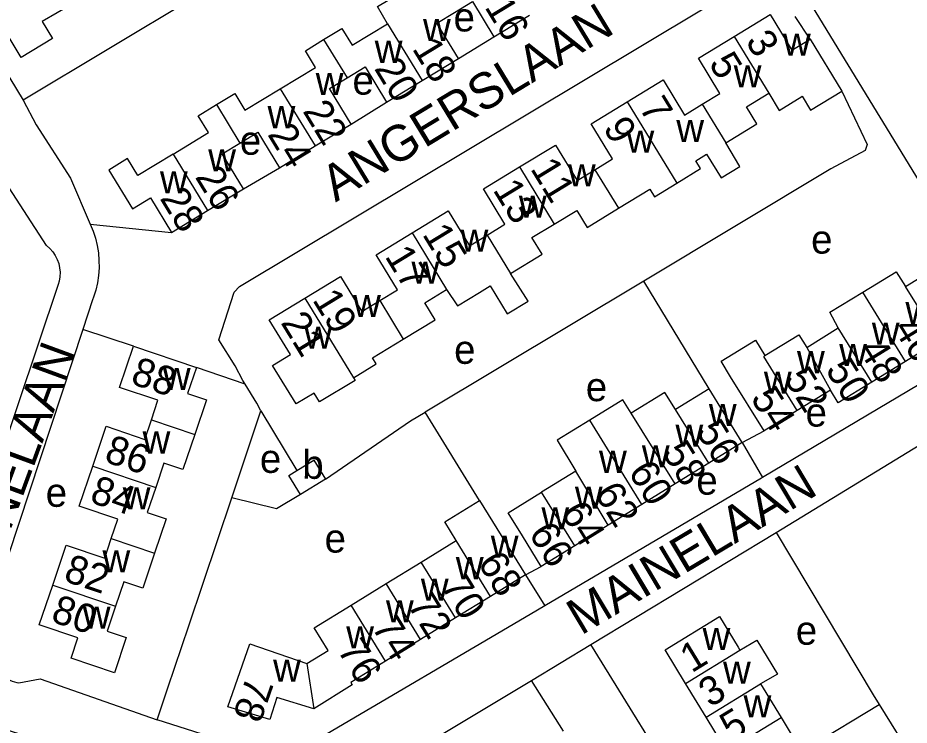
# Model space of a CAD drawing. Extents: x 157768 to 159790, y 387230 to 389604.
# Drawn here: x 158224.1 to 158348.2, y 388360.7 to 388459.2 of the extents above; entities that cross this region are included whole.
import ezdxf

# ---------------------------------------------------------------- set-up
doc = ezdxf.new("R2010")
doc.units = 0
for name, color, linetype in [('BLT_Basislijn', 7, 'Continuous'), ('BLT_Bebouwing', 7, 'Continuous'), ('BLT_Centroide', 7, 'Continuous'), ('BLT_Huisnummer', 7, 'Continuous'), ('BLT_Huisnummer_ tussenligend', 7, 'Continuous'), ('BLT_Onderverdeling_panden', 7, 'Continuous'), ('BLT_Straatnaam', 7, 'Continuous')]:
    doc.layers.add(name, color=color, linetype=linetype)

msp = doc.modelspace()

# ---------------------------------------------------------------- linework, layer by layer
at = {"layer": 'BLT_Basislijn'}
for p, q in [((158304.74, 388495.73), (158224.85, 388447.7)), ((158212.8, 388467.55), (158224.85, 388447.7)), ((158228.09, 388427.45), (158207.21, 388459.77)), ((158334.4, 388456.22), (158332.34, 388459.35)), ((158285.45, 388453.52), (158290.4, 388456.54)), ((158270.51, 388444.39), (158275.46, 388447.45)), ((158255.51, 388435.36), (158260.52, 388438.31)), ((158234.19, 388430.43), (158245.51, 388429.28)), ((158311.26, 388422.52), (158280.82, 388404.27)), ((158320.33, 388407.51), (158311.26, 388422.52)), ((158229.72, 388422.06), (158213.16, 388372.67)), ((158234.53, 388419.89), (158233.16, 388415.76)), ((158233.16, 388415.76), (158219.39, 388374.05)), ((158240.2, 388413.45), (158233.16, 388415.76)), ((158362.4, 388415.74), (158327.79, 388395.17)), ((158255.76, 388408.14), (158248.97, 388410.49)), ((158253.89, 388392.34), (158257.96, 388404.43)), ((158288.4, 388391.97), (158280.82, 388404.27)), ((158324.95, 388400.02), (158327.99, 388401.64)), ((158324.95, 388400.02), (158327.79, 388395.17)), ((158303.89, 388371.88), (158329.67, 388387.52)), ((158294.79, 388381.61), (158296.97, 388382.76)), ((158294.79, 388381.61), (158297.47, 388377.27)), ((158295.63, 388366.87), (158303.89, 388371.88)), ((158300.07, 388359.82), (158295.63, 388366.87)), ((158333.21, 388357.04), (158344.03, 388363.53))]:
    msp.add_line(p, q, dxfattribs=at)
for points in [[(158255.76, 388408.14), (158255.42, 388408.68), (158254.36, 388410.69), (158252.11, 388414.33), (158254.23, 388420.97), (158254.99, 388421.77), (158327.25, 388465.12), (158328.19, 388465.65), (158328.83, 388464.68)], [(158360.28, 388419.09), (158358.56, 388421.8), (158334.74, 388460.77)], [(158338.81, 388448.98), (158342.33, 388441.54), (158342.05, 388440.69), (158337.29, 388438.17), (158311.26, 388422.52)], [(158224.85, 388447.7), (158226.67, 388444.26), (158231.45, 388436.84), (158234.19, 388430.43)], [(158234.19, 388430.43), (158234.59, 388429.47), (158234.91, 388428.48), (158235.16, 388427.47), (158235.33, 388426.44), (158235.41, 388425.4), (158235.42, 388424.35), (158235.35, 388423.31), (158235.2, 388422.28), (158234.97, 388421.27), (158234.66, 388420.27), (158234.53, 388419.89)], [(158228.09, 388427.45), (158228.56, 388427.05), (158228.97, 388426.59), (158229.32, 388426.08), (158229.6, 388425.54), (158229.81, 388424.96), (158229.94, 388424.35), (158229.99, 388423.74), (158229.96, 388423.12), (158229.86, 388422.51), (158229.72, 388422.06)], [(158257.96, 388404.43), (158257.41, 388405.53), (158255.76, 388408.14)], [(158257.96, 388404.43), (158262.94, 388396.12)], [(158266.94, 388394.92), (158278.76, 388403.04), (158280.82, 388404.27)], [(158329.67, 388387.52), (158351.49, 388400.82), (158354.62, 388401.86), (158356.15, 388401.86), (158358.13, 388401.3), (158360.43, 388398.73), (158376, 388372.54), (158376.85, 388371.15)], [(158327.79, 388395.17), (158327.62, 388395.07), (158297.47, 388377.27)], [(158263.46, 388392.8), (158260.12, 388390.79), (158253.89, 388392.34)], [(158243.5, 388361.42), (158244.99, 388365.88), (158247.93, 388374.52), (158253.89, 388392.34)], [(158329.67, 388387.52), (158343.18, 388364.91), (158344.03, 388363.53)], [(158297.47, 388377.27), (158295.43, 388376.07), (158265.59, 388358.55), (158261.05, 388357.55), (158254.9, 388357.79), (158243.5, 388361.42)], [(158219.39, 388374.05), (158219.25, 388373.36), (158219.2, 388372.67), (158219.23, 388371.97), (158219.33, 388371.28), (158219.52, 388370.61), (158219.78, 388369.97), (158220.11, 388369.35), (158220.51, 388368.78), (158220.98, 388368.26), (158221.5, 388367.8), (158222.07, 388367.4), (158222.68, 388367.07), (158223.32, 388366.8), (158223.99, 388366.62), (158224.27, 388366.57)], [(158318.74, 388347.85), (158317.77, 388349.42), (158303.89, 388371.88)], [(158216.32, 388362.01), (158245.98, 388352.56), (158258.32, 388349.1), (158262.21, 388348.81), (158266.48, 388349.4), (158295.63, 388366.87)], [(158224.27, 388366.57), (158227.24, 388367.13), (158243.5, 388361.42)], [(158344.03, 388363.53), (158348.79, 388355.84), (158349.73, 388354.3)]]:
    msp.add_lwpolyline(points, dxfattribs=at)
at = {"layer": 'BLT_Bebouwing'}
for p, q in [((158290.4, 388456.54), (158295.36, 388459.56)), ((158334.4, 388456.22), (158338.81, 388448.98)), ((158280.4, 388450.46), (158285.45, 388453.52)), ((158260.52, 388438.31), (158265.49, 388441.34)), ((158250.53, 388432.33), (158255.51, 388435.36)), ((158245.51, 388429.28), (158250.53, 388432.33)), ((158333.93, 388413.28), (158338.33, 388415.99)), ((158352.35, 388414.2), (158347.67, 388411.31)), ((158240.2, 388413.45), (158248.97, 388410.49)), ((158347.67, 388411.31), (158342.99, 388408.43)), ((158320.33, 388407.51), (158315.67, 388404.63)), ((158337.22, 388407.33), (158332.6, 388404.48)), ((158332.6, 388404.48), (158327.99, 388401.64)), ((158324.95, 388400.02), (158320.29, 388397.14)), ((158320.29, 388397.14), (158315.63, 388394.27)), ((158301.77, 388396.06), (158297.02, 388393.13)), ((158266.94, 388394.92), (158263.46, 388392.8)), ((158315.63, 388394.27), (158310.96, 388391.39)), ((158288.4, 388391.97), (158294.79, 388381.61)), ((158310.96, 388391.39), (158306.3, 388388.51)), ((158306.3, 388388.51), (158301.64, 388385.64)), ((158280.25, 388383.39), (158285.12, 388386.39)), ((158301.64, 388385.64), (158296.97, 388382.76)), ((158275.39, 388380.39), (158280.25, 388383.39)), ((158294.79, 388381.61), (158289.92, 388378.61)), ((158270.52, 388377.39), (158275.39, 388380.39)), ((158289.92, 388378.61), (158285.06, 388375.61)), ((158285.06, 388375.61), (158280.19, 388372.6)), ((158280.19, 388372.6), (158275.32, 388369.6)), ((158319.93, 388361.8), (158317.07, 388366.49)), ((158327.5, 388366.41), (158330.36, 388361.72)), ((158322.79, 388357.11), (158319.93, 388361.8)), ((158330.36, 388361.72), (158333.21, 388357.04))]:
    msp.add_line(p, q, dxfattribs=at)
for points in [[(158231.67, 388461.1), (158227.5, 388458.67), (158228.95, 388456.3), (158224.6, 388453.65), (158221.07, 388459.45), (158224.94, 388461.8), (158220.75, 388468.67), (158225.35, 388471.47)], [(158275.59, 388458.36), (158274.18, 388460.75), (158279.08, 388463.73), (158281.64, 388465.29)], [(158284.9, 388459.93), (158287.41, 388461.45), (158290.4, 388456.54)], [(158285.45, 388453.52), (158282.46, 388458.44), (158284.9, 388459.93)], [(158323.84, 388456.59), (158328.83, 388459.64), (158331.86, 388454.67), (158334.4, 388456.22)], [(158266.69, 388456.15), (158269.24, 388457.71), (158270.67, 388455.36), (158275.59, 388458.36)], [(158260.64, 388449.3), (158265.55, 388452.28), (158264.14, 388454.6), (158266.69, 388456.15)], [(158319.39, 388447.14), (158321.84, 388448.64), (158318.85, 388453.55), (158323.84, 388456.59)], [(158269.94, 388450.81), (158272.47, 388452.35), (158275.46, 388447.45)], [(158270.51, 388444.39), (158267.51, 388449.33), (158269.94, 388450.81)], [(158275.46, 388447.45), (158280.4, 388450.46)], [(158308.93, 388447.49), (158313.94, 388450.54), (158316.93, 388445.64), (158319.39, 388447.14)], [(158251.77, 388447.09), (158254.32, 388448.65), (158255.74, 388446.32), (158260.64, 388449.3)], [(158322.65, 388441.79), (158326.98, 388444.43), (158325.55, 388446.77), (158328.67, 388448.67)], [(158328.67, 388448.67), (158330.09, 388446.29), (158333.24, 388448.21), (158333.31, 388448.25), (158334.48, 388446.34), (158338.81, 388448.98)], [(158304.43, 388438.03), (158306.91, 388439.53), (158303.92, 388444.43), (158308.93, 388447.49)], [(158245.74, 388440.21), (158250.64, 388443.2), (158249.21, 388445.54), (158251.77, 388447.09)], [(158265.49, 388441.34), (158270.51, 388444.39)], [(158255.03, 388441.73), (158257.51, 388443.24), (158260.52, 388438.31)], [(158255.51, 388435.36), (158252.55, 388440.22), (158255.03, 388441.73)], [(158293.93, 388438.41), (158298.94, 388441.46), (158301.96, 388436.52), (158304.43, 388438.03)], [(158318.51, 388439.27), (158320, 388440.17), (158322.01, 388436.88), (158324.62, 388438.48), (158322.65, 388441.79)], [(158245.74, 388440.21), (158240.83, 388437.23), (158239.4, 388439.58), (158236.77, 388437.98), (158240.06, 388432.58), (158242.57, 388434.11), (158245.51, 388429.28)], [(158315.83, 388436.16), (158319.16, 388438.19), (158318.51, 388439.27)], [(158289.46, 388428.93), (158291.93, 388430.43), (158288.92, 388435.35), (158293.93, 388438.41)], [(158307.71, 388432.65), (158312.1, 388435.32), (158312.74, 388434.27), (158315.83, 388436.16)], [(158279.02, 388429.24), (158284.03, 388432.29), (158287, 388427.42), (158289.46, 388428.93)], [(158298.78, 388430.45), (158301.92, 388432.36), (158303.37, 388430), (158307.71, 388432.65)], [(158292.72, 388423.58), (158297.1, 388426.25), (158295.69, 388428.57), (158298.78, 388430.45)], [(158274.49, 388419.8), (158276.97, 388421.31), (158274, 388426.18), (158279.02, 388429.24)], [(158283.81, 388421.36), (158285.33, 388419.07), (158288.37, 388420.92), (158289.87, 388421.84), (158292.24, 388417.96), (158295.15, 388419.73), (158292.72, 388423.58)], [(158341.76, 388420.99), (158346.38, 388423.81), (158347.68, 388421.76)], [(158347.68, 388421.76), (158352.35, 388424.64), (158357.02, 388417.08)], [(158264.08, 388420.15), (158269.04, 388423.17), (158272.02, 388418.3), (158274.49, 388419.8)], [(158277.77, 388414.44), (158282.2, 388417.14), (158280.76, 388419.5), (158283.81, 388421.36)], [(158270.85, 388409.05), (158271.07, 388408.69), (158266.12, 388405.68), (158265.36, 388406.92), (158262.85, 388405.4), (158259.58, 388410.75), (158262.07, 388412.27), (158259.11, 388417.12), (158264.08, 388420.15)], [(158338.33, 388415.99), (158337.16, 388418.18), (158341.76, 388420.99)], [(158328.12, 388412.13), (158332.84, 388415.04), (158333.93, 388413.28)], [(158270.85, 388409.05), (158274, 388410.97), (158273.48, 388411.83), (158277.77, 388414.44)], [(158327.99, 388401.64), (158323.34, 388409.18), (158322, 388411.34), (158326.8, 388414.3), (158328.12, 388412.13)], [(158242.71, 388403.19), (158243.62, 388405.91), (158238.26, 388407.71), (158240.2, 388413.45)], [(158248.97, 388410.49), (158247.74, 388406.86), (158250.37, 388405.97), (158248.75, 388401.15)], [(158324.95, 388400.02), (158322.33, 388404.27), (158320.33, 388407.51)], [(158342.99, 388408.43), (158338.32, 388405.55), (158337.22, 388407.33)], [(158315.67, 388404.63), (158314.2, 388407.01), (158309.5, 388404.1)], [(158309.5, 388404.1), (158308.34, 388405.99), (158303.75, 388403.16)], [(158234.54, 388396.74), (158236.41, 388402.29), (158241.79, 388400.47), (158242.71, 388403.19)], [(158303.75, 388403.16), (158299.18, 388400.34), (158301.77, 388396.06)], [(158248.75, 388401.15), (158247.1, 388396.27), (158244.45, 388397.16), (158243.31, 388393.78)], [(158262.94, 388396.12), (158265.32, 388397.57), (158266.94, 388394.92)], [(158237.13, 388386.65), (158238.05, 388389.37), (158232.67, 388391.19), (158234.54, 388396.74)], [(158263.46, 388392.8), (158261.84, 388395.45), (158262.94, 388396.12)], [(158243.31, 388393.78), (158242.14, 388390.3), (158244.76, 388389.41), (158243.14, 388384.62)], [(158296.97, 388382.76), (158294.35, 388387.02), (158292.35, 388390.25), (158297.02, 388393.13)], [(158285.12, 388386.39), (158283.58, 388389), (158288.4, 388391.97)], [(158228.97, 388380.18), (158230.84, 388385.73), (158236.21, 388383.92), (158237.13, 388386.65)], [(158243.14, 388384.62), (158241.5, 388379.77), (158238.88, 388380.65), (158237.73, 388377.23)], [(158237.73, 388377.23), (158236.56, 388373.76), (158239.21, 388372.86), (158237.56, 388367.98), (158231.53, 388370.01), (158232.48, 388372.82), (158227.1, 388374.63), (158228.97, 388380.18)], [(158264.33, 388369.24), (158267.33, 388371.09), (158265.39, 388374.22), (158270.52, 388377.39)], [(158317.07, 388366.49), (158314.21, 388371.18), (158321.78, 388375.79), (158324.39, 388371.52), (158324.64, 388371.1)], [(158265.3, 388362.96), (158260.15, 388364.53), (158259.22, 388361.47), (158253.37, 388363.24), (158256.4, 388371.99), (158264.33, 388369.24)], [(158324.64, 388371.1), (158326.97, 388372.52), (158329.85, 388367.76), (158327.5, 388366.41)], [(158275.32, 388369.6), (158270.45, 388366.6), (158270.66, 388366.27), (158265.3, 388362.96)]]:
    msp.add_lwpolyline(points, dxfattribs=at)
at = {"layer": 'BLT_Onderverdeling_panden'}
for p, q in [((158275.59, 388458.36), (158280.4, 388450.46)), ((158266.69, 388456.15), (158269.94, 388450.81)), ((158323.84, 388456.59), (158328.67, 388448.67)), ((158260.64, 388449.3), (158265.49, 388441.34)), ((158308.93, 388447.49), (158315.83, 388436.16)), ((158319.39, 388447.14), (158322.65, 388441.79)), ((158251.77, 388447.09), (158255.03, 388441.73)), ((158245.74, 388440.21), (158250.53, 388432.33)), ((158293.93, 388438.41), (158298.78, 388430.45)), ((158304.43, 388438.03), (158307.71, 388432.65)), ((158279.02, 388429.24), (158283.81, 388421.36)), ((158289.46, 388428.93), (158292.72, 388423.58)), ((158352.35, 388414.2), (158347.68, 388421.76)), ((158264.08, 388420.15), (158270.85, 388409.05)), ((158347.67, 388411.31), (158341.76, 388420.99)), ((158274.49, 388419.8), (158277.77, 388414.44)), ((158342.99, 388408.43), (158338.33, 388415.99)), ((158333.93, 388413.28), (158337.22, 388407.33)), ((158315.63, 388394.27), (158309.5, 388404.1)), ((158320.29, 388397.14), (158315.67, 388404.63)), ((158242.71, 388403.19), (158248.75, 388401.15)), ((158310.96, 388391.39), (158303.75, 388403.16)), ((158234.54, 388396.74), (158243.31, 388393.78)), ((158306.3, 388388.51), (158301.77, 388396.06)), ((158301.64, 388385.64), (158297.02, 388393.13)), ((158237.13, 388386.65), (158243.14, 388384.62)), ((158289.92, 388378.61), (158285.12, 388386.39)), ((158285.06, 388375.61), (158280.25, 388383.39)), ((158228.97, 388380.18), (158237.73, 388377.23)), ((158280.19, 388372.6), (158275.39, 388380.39)), ((158275.32, 388369.6), (158270.52, 388377.39)), ((158317.07, 388366.49), (158324.64, 388371.1)), ((158264.33, 388369.24), (158265.3, 388362.96)), ((158319.93, 388361.8), (158327.5, 388366.41)), ((158322.79, 388357.11), (158330.36, 388361.72))]:
    msp.add_line(p, q, dxfattribs=at)
msp.add_lwpolyline([(158332.6, 388404.48), (158327.95, 388412.03), (158328.12, 388412.13)], dxfattribs=at)

# ---------------------------------------------------------------- texts
at = {"layer": 'BLT_Centroide'}
for s, p in [('e', (158284.77, 388457.28)), ('w', (158280.52, 388455.95)), ('w', (158273.8, 388452.91)), ('w', (158330.63, 388453.91)), ('w', (158323.77, 388449.5)), ('w', (158265.58, 388448.42)), ('e', (158270.7, 388448.48)), ('w', (158258.88, 388443.81)), ('w', (158315.78, 388441.88)), ('w', (158308.84, 388440.39)), ('e', (158255.02, 388440.11)), ('w', (158250.62, 388437.78)), ('w', (158300.7, 388435.72)), ('w', (158243.9, 388434.75)), ('w', (158293.86, 388431.33)), ('w', (158285.74, 388426.59)), ('e', (158334.54, 388426.34)), ('w', (158278.91, 388422.14)), ('w', (158270.79, 388417.5)), ('w', (158347.67, 388416.53)), ('w', (158264, 388413.09)), ('w', (158343, 388413.66)), ('e', (158284.85, 388410.99)), ('w', (158338.45, 388410.7)), ('w', (158332.58, 388409.69)), ('w', (158244.31, 388407.36)), ('w', (158327.97, 388406.83)), ('e', (158303.18, 388405.79)), ('w', (158320.31, 388402.33)), ('e', (158333.77, 388402.25)), ('w', (158315.66, 388399.45)), ('w', (158241.48, 388398.5)), ('e', (158257.81, 388395.8)), ('b', (158263.71, 388394.98)), ('w', (158305.02, 388395.81)), ('w', (158310.98, 388396.58)), ('e', (158318.56, 388392.77)), ('e', (158228, 388391.08)), ('w', (158238.72, 388390.73)), ('w', (158301.66, 388390.83)), ('w', (158297, 388387.95)), ('e', (158266.82, 388384.7)), ('w', (158289.95, 388384)), ('w', (158235.9, 388381.94)), ('w', (158285.09, 388381)), ('w', (158280.22, 388378)), ('w', (158275.36, 388375)), ('w', (158233.16, 388374.12)), ('w', (158269.83, 388371.36)), ('w', (158319.43, 388371.12)), ('e', (158332.41, 388371.87)), ('w', (158259.65, 388366.72)), ('w', (158322.28, 388366.44)), ('w', (158325.14, 388361.75))]:
    msp.add_text(s, height=4, dxfattribs=at).set_placement(p)
at = {"layer": 'BLT_Huisnummer'}
for s, rotation, p in [('3', 301.3715, (158325.33, 388455.93)), ('18', 301.3165, (158278.93, 388454.9)), ('7', 301.3715, (158310.52, 388446.66)), ('22', 301.3165, (158263.7, 388446.2)), ('11', 301.3774, (158295.39, 388438.18)), ('28', 301.3165, (158243.81, 388434.05)), ('15', 301.3774, (158280.35, 388429.03)), ('21', 301.3774, (158260.64, 388416.74)), ('48', 301.6704, (158341.03, 388413.01)), ('88', 341.3686, (158239.66, 388408.28)), ('54', 301.6704, (158326.04, 388406.23)), ('56', 301.6651, (158318.4, 388401.64)), ('60', 301.6651, (158309, 388395.95)), ('84', 341.3686, (158233.97, 388391.77)), ('66', 301.6651, (158295.15, 388387.37)), ('68', 301.6707, (158288.05, 388383.3)), ('72', 301.6707, (158278.28, 388377.42)), ('80', 341.3686, (158228.56, 388375.16)), ('76', 301.6707, (158268.51, 388371.15)), ('1', 31.364, (158317.9, 388367.87)), ('78', 250.9018, (158255.99, 388367.66))]:
    msp.add_text(s, height=4, rotation=rotation, dxfattribs=at).set_placement(p)
at = {"layer": 'BLT_Huisnummer_ tussenligend'}
for s, rotation, p in [('16', 301.3165, (158289.02, 388460.69)), ('20', 301.3165, (158273.65, 388452.13)), ('5', 301.3715, (158320.22, 388452.84)), ('9', 301.3774, (158305.51, 388443.85)), ('24', 301.3165, (158258.8, 388442.96)), ('26', 301.3165, (158248.71, 388437.03)), ('13', 301.3774, (158290.17, 388435.23)), ('17', 301.3774, (158275.13, 388425.97)), ('19', 301.3774, (158265.05, 388419.91)), ('46', 301.6704, (158345.89, 388415.96)), ('50', 301.6704, (158336.45, 388410.19)), ('52', 301.6704, (158330.67, 388408.96)), ('86', 341.3686, (158235.99, 388397.42)), ('58', 301.6651, (158313.69, 388398.67)), ('62', 301.6651, (158304.29, 388392.97)), ('64', 301.6651, (158299.58, 388390.29)), ('82', 341.3686, (158230.33, 388380.81)), ('70', 301.6707, (158282.93, 388380.07)), ('74', 301.6707, (158273.3, 388374.34)), ('3', 31.364, (158320.48, 388363.06)), ('5', 31.364, (158323.44, 388358.34))]:
    msp.add_text(s, height=4, rotation=rotation, dxfattribs=at).set_placement(p)
at = {"layer": 'BLT_Straatnaam'}
for s, rotation, p in [('ANGERSLAAN', 31.2722, (158268.35, 388433.45)), ('MAINELAAN', 69.825, (158218.94, 388376.48)), ('MAINELAAN', 30.825, (158302.52, 388373.12))]:
    msp.add_text(s, height=5, rotation=rotation, dxfattribs=at).set_placement(p)

doc.saveas('drawing.dxf')
